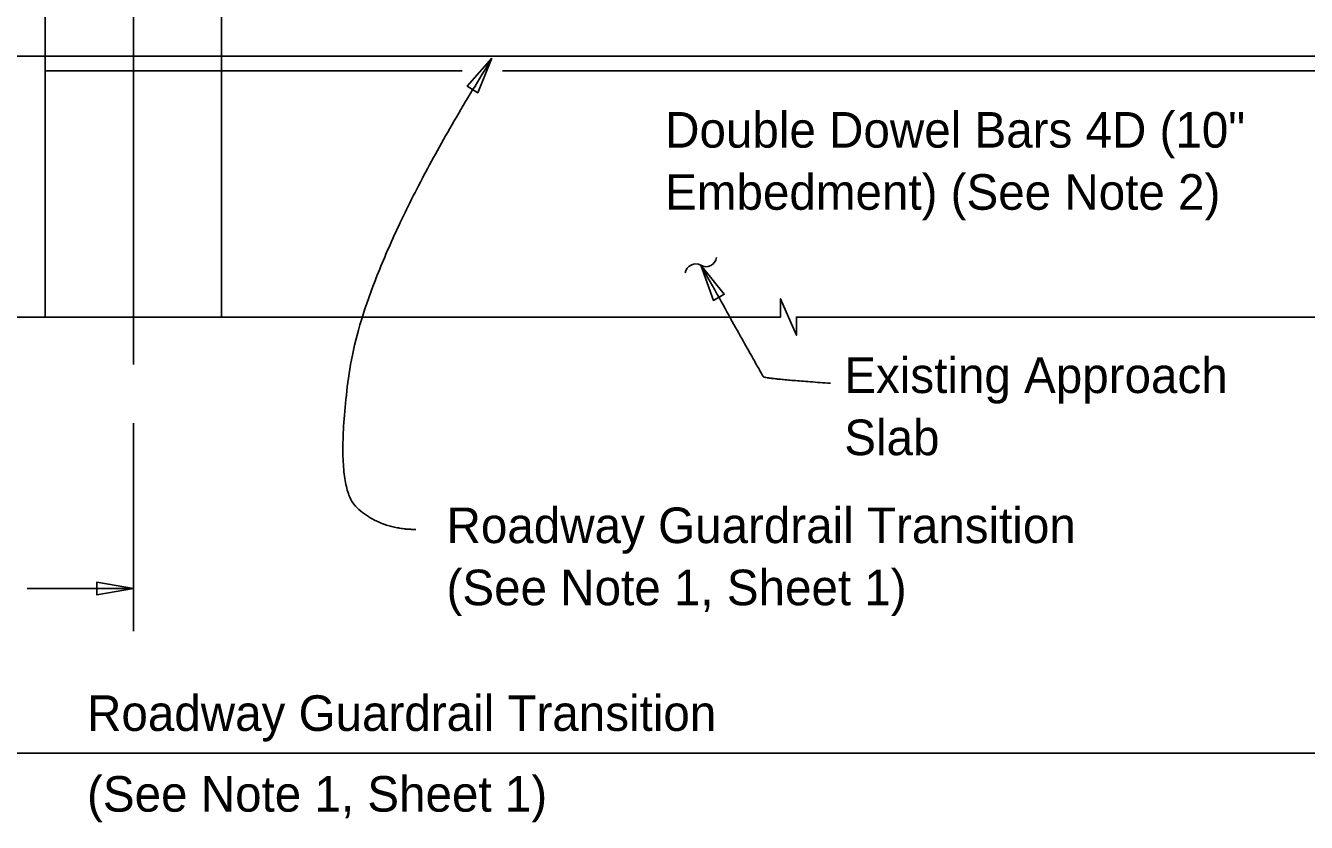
# Model space of a CAD drawing. Extents: x 21526.6 to 21595.9, y 56117 to 56157.3.
# Drawn here: x 21554.19 to 21561.45, y 56142.39 to 56146.9 of the extents above; entities that cross this region are included whole.
import ezdxf

# ---------------------------------------------------------------- set-up
doc = ezdxf.new("R2010")
doc.units = 0
for name, color, linetype in [('AdhocPoint_dp', 7, 'Continuous'), ('Patterning', 7, 'Continuous'), ('PlotBorder_dp', 7, 'Continuous')]:
    doc.layers.add(name, color=color, linetype=linetype)

msp = doc.modelspace()

# ---------------------------------------------------------------- linework, layer by layer
at = {"layer": 'AdhocPoint_dp'}
for p, q in [((21554.3018, 56145.2536), (21554.3018, 56149.7195)), ((21555.3018, 56145.2536), (21555.3018, 56148.546)), ((21554.3018, 56146.6482), (21556.6644, 56146.6482)), ((21556.8934, 56146.6482), (21565.9973, 56146.6482))]:
    msp.add_line(p, q, dxfattribs=at)
at = {"layer": 'Patterning'}
msp.add_line((21552.8484, 56146.7315), (21566.2337, 56146.7315), dxfattribs=at)
at = {"layer": 'PlotBorder_dp'}
for p, q in [((21554.8018, 56147.4803), (21554.8018, 56144.9856)), ((21554.8018, 56144.6532), (21554.8018, 56143.4731)), ((21554.1998, 56143.7154), (21554.8018, 56143.7154))]:
    msp.add_line(p, q, dxfattribs=at)
for points in [[(21556.8339, 56146.7196), (21556.6935, 56146.5618), (21556.7534, 56146.5243)], [(21558.0183, 56145.5472), (21558.0888, 56145.3481), (21558.1504, 56145.3824)], [(21554.8018, 56143.7154), (21554.5935, 56143.7507), (21554.5935, 56143.6801)]]:
    msp.add_lwpolyline(points, close=True, dxfattribs=at)
for points in [[(21553.5912, 56145.2536), (21558.4694, 56145.2536), (21558.4694, 56145.3569), (21558.5144, 56145.2536), (21558.5594, 56145.1503), (21558.5594, 56145.2536), (21560.8244, 56145.2536)], [(21560.8244, 56145.2536), (21563.2763, 56145.2536), (21563.2763, 56145.3569), (21563.3213, 56145.2536), (21563.3663, 56145.1503), (21563.3663, 56145.2536), (21566.1735, 56145.2536)], [(21546.0419, 56142.7836), (21550.1141, 56142.7836), (21550.1141, 56142.8869), (21550.1591, 56142.7836), (21550.2041, 56142.6803), (21550.2041, 56142.7836), (21562.1372, 56142.7836)]]:
    msp.add_lwpolyline(points, dxfattribs=at)
for centre, start, end in [((21558.0471, 56145.5986), 240.3192, 352.04642), ((21557.9881, 56145.495), 60.3192, 172.04642)]:
    msp.add_arc(centre, 0.0596, start, end, dxfattribs=at)
for points in [[(21556.4023, 56144.0502), (21556.2084, 56144.0502), (21555.9353, 56144.288), (21556.1115, 56145.5655), (21556.8339, 56146.7196)], [(21558.7533, 56144.8783), (21558.3801, 56144.9047), (21558.3646, 56144.925), (21558.0183, 56145.5472)]]:
    msp.add_open_spline(points, degree=2, dxfattribs=at)

# ---------------------------------------------------------------- texts
for s, p in [('Double Dowel Bars 4D (10" ', (21557.8152, 56146.2135)), ('Embedment) (See Note 2)', (21557.8152, 56145.8615)), ('Existing Approach ', (21558.8305, 56144.8231)), ('Slab', (21558.8305, 56144.4711)), ('Roadway Guardrail Transition ', (21556.5764, 56143.9729)), ('(See Note 1, Sheet 1)', (21556.5764, 56143.6209)), ('Roadway Guardrail Transition', (21554.539, 56142.909)), ('(See Note 1, Sheet 1)', (21554.539, 56142.4514))]:
    msp.add_text(s, height=0.2016, dxfattribs=at).set_placement(p)

doc.saveas('drawing.dxf')
